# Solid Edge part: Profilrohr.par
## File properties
Username: bmolnar
Dokumentum tartalom típus: 0
Author: bmolnar
Last saved by: bmolnar
Revision: 92
Sűrűség: 0,000 kg/m^3
Pontosság: 0,990
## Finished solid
Body 1: solid body, 63 faces, 178 edges, 112 vertices.
  Faces by surface: cylinder 33, plane 30
  Edges by curve: line 112, circle 66
Bounding box of the edges (mm): 36.000 x 213.400 x 36.000, from (-18, -204.15, -18) to (18, 9.25, 18).
Cylindrical faces by radius (mm): R0.2 x12, R0.5 x12, R3.775 x4, R4.5 x4, R10 x1
Planar faces by outward normal: +x 7, +y 1, +z 7, -x 7, -y 1, -z 7
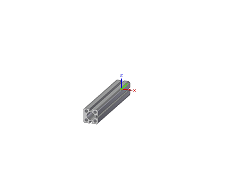
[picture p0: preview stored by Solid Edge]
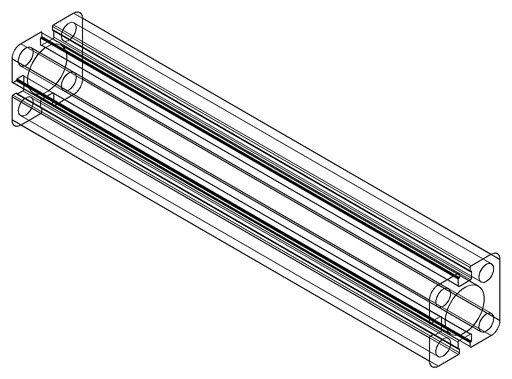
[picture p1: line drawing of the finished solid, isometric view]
